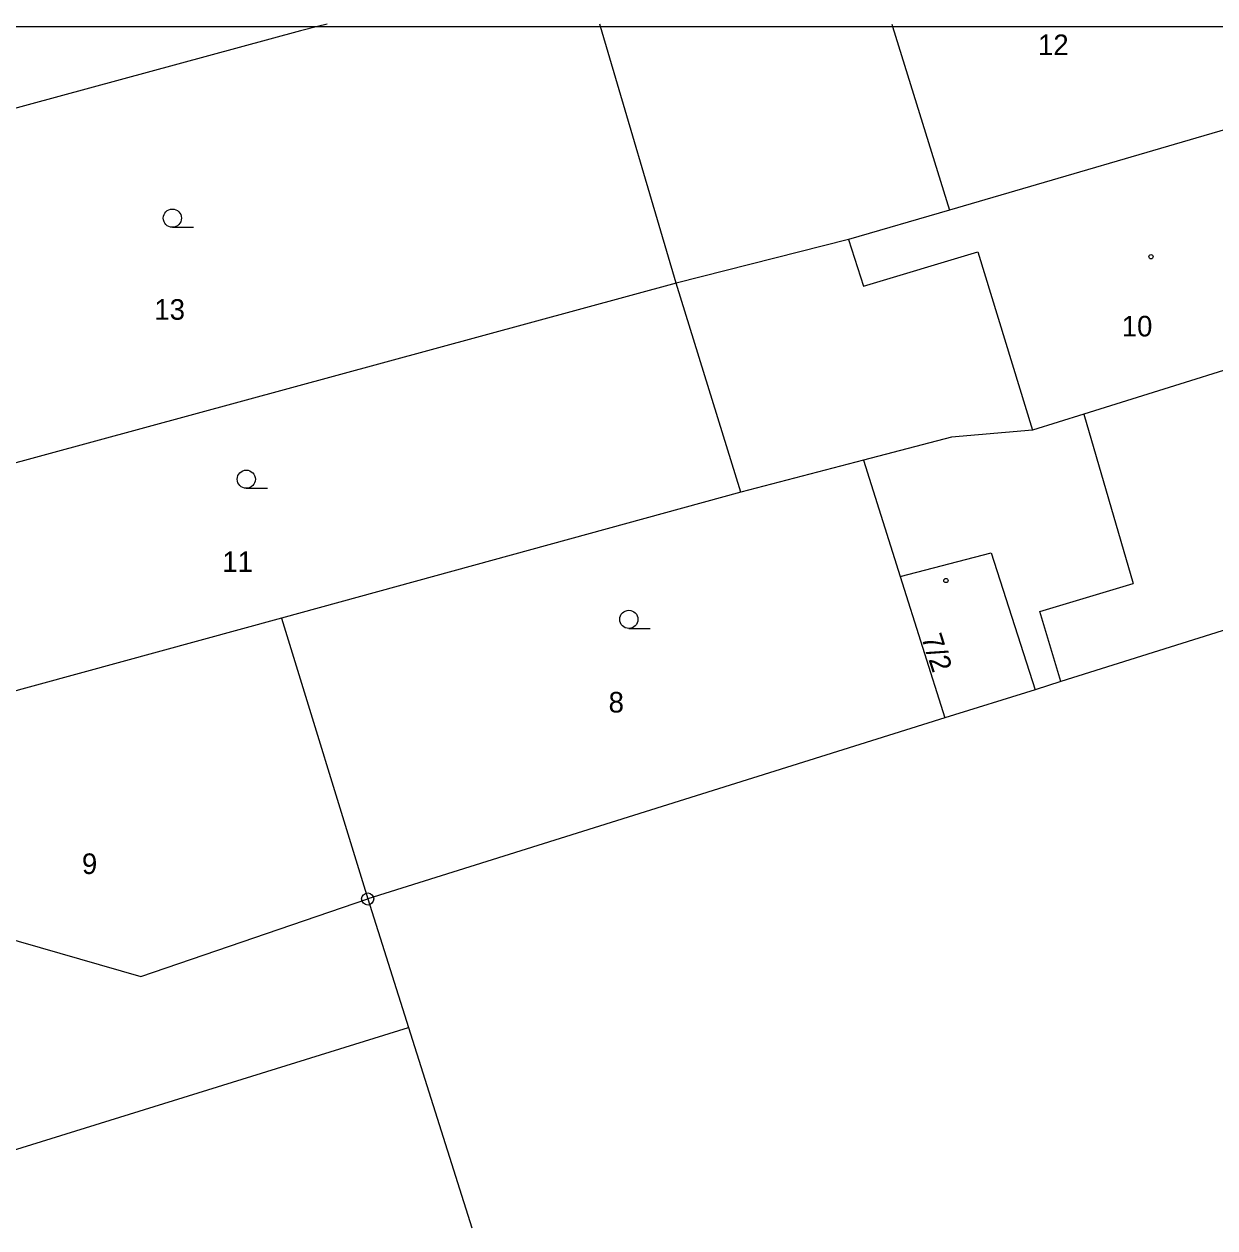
# Model space of a CAD drawing. Extents: x -599866 to -590076, y -1178039 to -1154526.
# Drawn here: x -599691.83 to -599642.65, y -1154756.06 to -1154706.35 of the extents above; entities that cross this region are included whole.
import ezdxf

# ---------------------------------------------------------------- set-up
doc = ezdxf.new("R2010")
doc.units = 0
doc.layers.add('KN', color=7, linetype='Continuous')
doc.layers.add('Rám', color=7, linetype='Continuous')

msp = doc.modelspace()

# ---------------------------------------------------------------- linework, layer by layer
at = {"layer": 'KN'}
for p, q in [((-599680.42, -1154706.63), (-599707.82, -1154714.06)), ((-599679.712, -1154706.45), (-599680.42, -1154706.63)), ((-599679.319, -1154706.35), (-599679.712, -1154706.45)), ((-599668.032, -1154706.45), (-599668.061, -1154706.35)), ((-599664.9, -1154717.05), (-599668.032, -1154706.45)), ((-599655.998, -1154706.35), (-599655.967, -1154706.45)), ((-599655.967, -1154706.45), (-599653.61, -1154714.03)), ((-599685.706, -1154714.74), (-599684.831, -1154714.74)), ((-599657.79, -1154715.25), (-599664.9, -1154717.05)), ((-599657.79, -1154715.25), (-599657.17, -1154717.17)), ((-599657.17, -1154717.17), (-599652.45, -1154715.76)), ((-599652.45, -1154715.76), (-599650.19, -1154723.12)), ((-599664.9, -1154717.05), (-599703.5, -1154727.55)), ((-599662.23, -1154725.68), (-599664.9, -1154717.05)), ((-599648.07, -1154722.46), (-599646.03, -1154729.45)), ((-599650.19, -1154723.12), (-599653.53, -1154723.41)), ((-599653.53, -1154723.41), (-599657.16, -1154724.36)), ((-599657.16, -1154724.36), (-599662.23, -1154725.68)), ((-599657.16, -1154724.36), (-599655.65, -1154729.16)), ((-599682.657, -1154725.52), (-599681.782, -1154725.52)), ((-599662.23, -1154725.68), (-599681.2, -1154730.88)), ((-599655.65, -1154729.16), (-599653.81, -1154735)), ((-599649.88, -1154730.61), (-599646.03, -1154729.45)), ((-599649.01, -1154733.5), (-599649.88, -1154730.61)), ((-599681.2, -1154730.88), (-599700.72, -1154736.23)), ((-599681.2, -1154730.88), (-599677.64, -1154742.48)), ((-599666.856, -1154731.31), (-599665.981, -1154731.31)), ((-599649.01, -1154733.5), (-599650.08, -1154733.84)), ((-599650.08, -1154733.84), (-599653.81, -1154735)), ((-599653.81, -1154735), (-599677.64, -1154742.48)), ((-599677.64, -1154742.48), (-599675.96, -1154747.79)), ((-599702.59, -1154756.065), (-599675.96, -1154747.79)), ((-599675.96, -1154747.79), (-599673.344, -1154756.065))]:
    msp.add_line(p, q, dxfattribs=at)
for points in [[(-599640.99, -1154710.34), (-599653.61, -1154714.03), (-599657.79, -1154715.25)], [(-599638.12, -1154719.35), (-599648.07, -1154722.46), (-599650.19, -1154723.12)], [(-599632.53, -1154723.79), (-599632.29, -1154725.63), (-599632.66, -1154726.9), (-599633.49, -1154728.16), (-599634.99, -1154729.1), (-599649.01, -1154733.5)], [(-599655.65, -1154729.16), (-599651.89, -1154728.18), (-599650.08, -1154733.84)], [(-599700.72, -1154736.23), (-599698.78, -1154742.3), (-599687.01, -1154745.68), (-599677.64, -1154742.48)]]:
    msp.add_lwpolyline(points, dxfattribs=at)
for centre, radius in [((-599685.706, -1154714.365), 0.375), ((-599645.293, -1154715.96), 0.0875), ((-599682.656, -1154725.145), 0.375), ((-599653.763, -1154729.33), 0.0875), ((-599666.856, -1154730.935), 0.375), ((-599677.64, -1154742.48), 0.25), ((-599677.64, -1154742.48), 0.0152)]:
    msp.add_circle(centre, radius, dxfattribs=at)
at = {"layer": 'Rám'}
msp.add_lwpolyline([(-599701.74, -1154706.45), (-599596.74, -1154706.45)], dxfattribs=at)

# ---------------------------------------------------------------- texts
at = {"layer": 'KN'}
for s, p in [('12', (-599649.957, -1154707.63)), ('13', (-599686.45, -1154718.56)), ('10', (-599646.5, -1154719.25)), ('11', (-599683.648, -1154728.98)), ('8', (-599667.692, -1154734.78)), ('9', (-599689.442, -1154741.45))]:
    msp.add_text(s, height=0.85, dxfattribs=at).set_placement(p)
msp.add_text('7/2', height=0.85, rotation=288, dxfattribs=at).set_placement((-599654.783, -1154731.68))

doc.saveas('drawing.dxf')
